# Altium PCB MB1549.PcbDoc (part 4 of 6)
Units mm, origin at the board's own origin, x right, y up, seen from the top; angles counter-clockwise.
Board outline 70 x 133.34 mm, 6 copper layers (Top Layer, Signal Layer 1, Signal Layer 2, Signal Layer 3, Signal Layer 4, Bottom Layer), stack 1.57 mm thick; 289 components, 250 nets, 1288 pads, 875 vias.
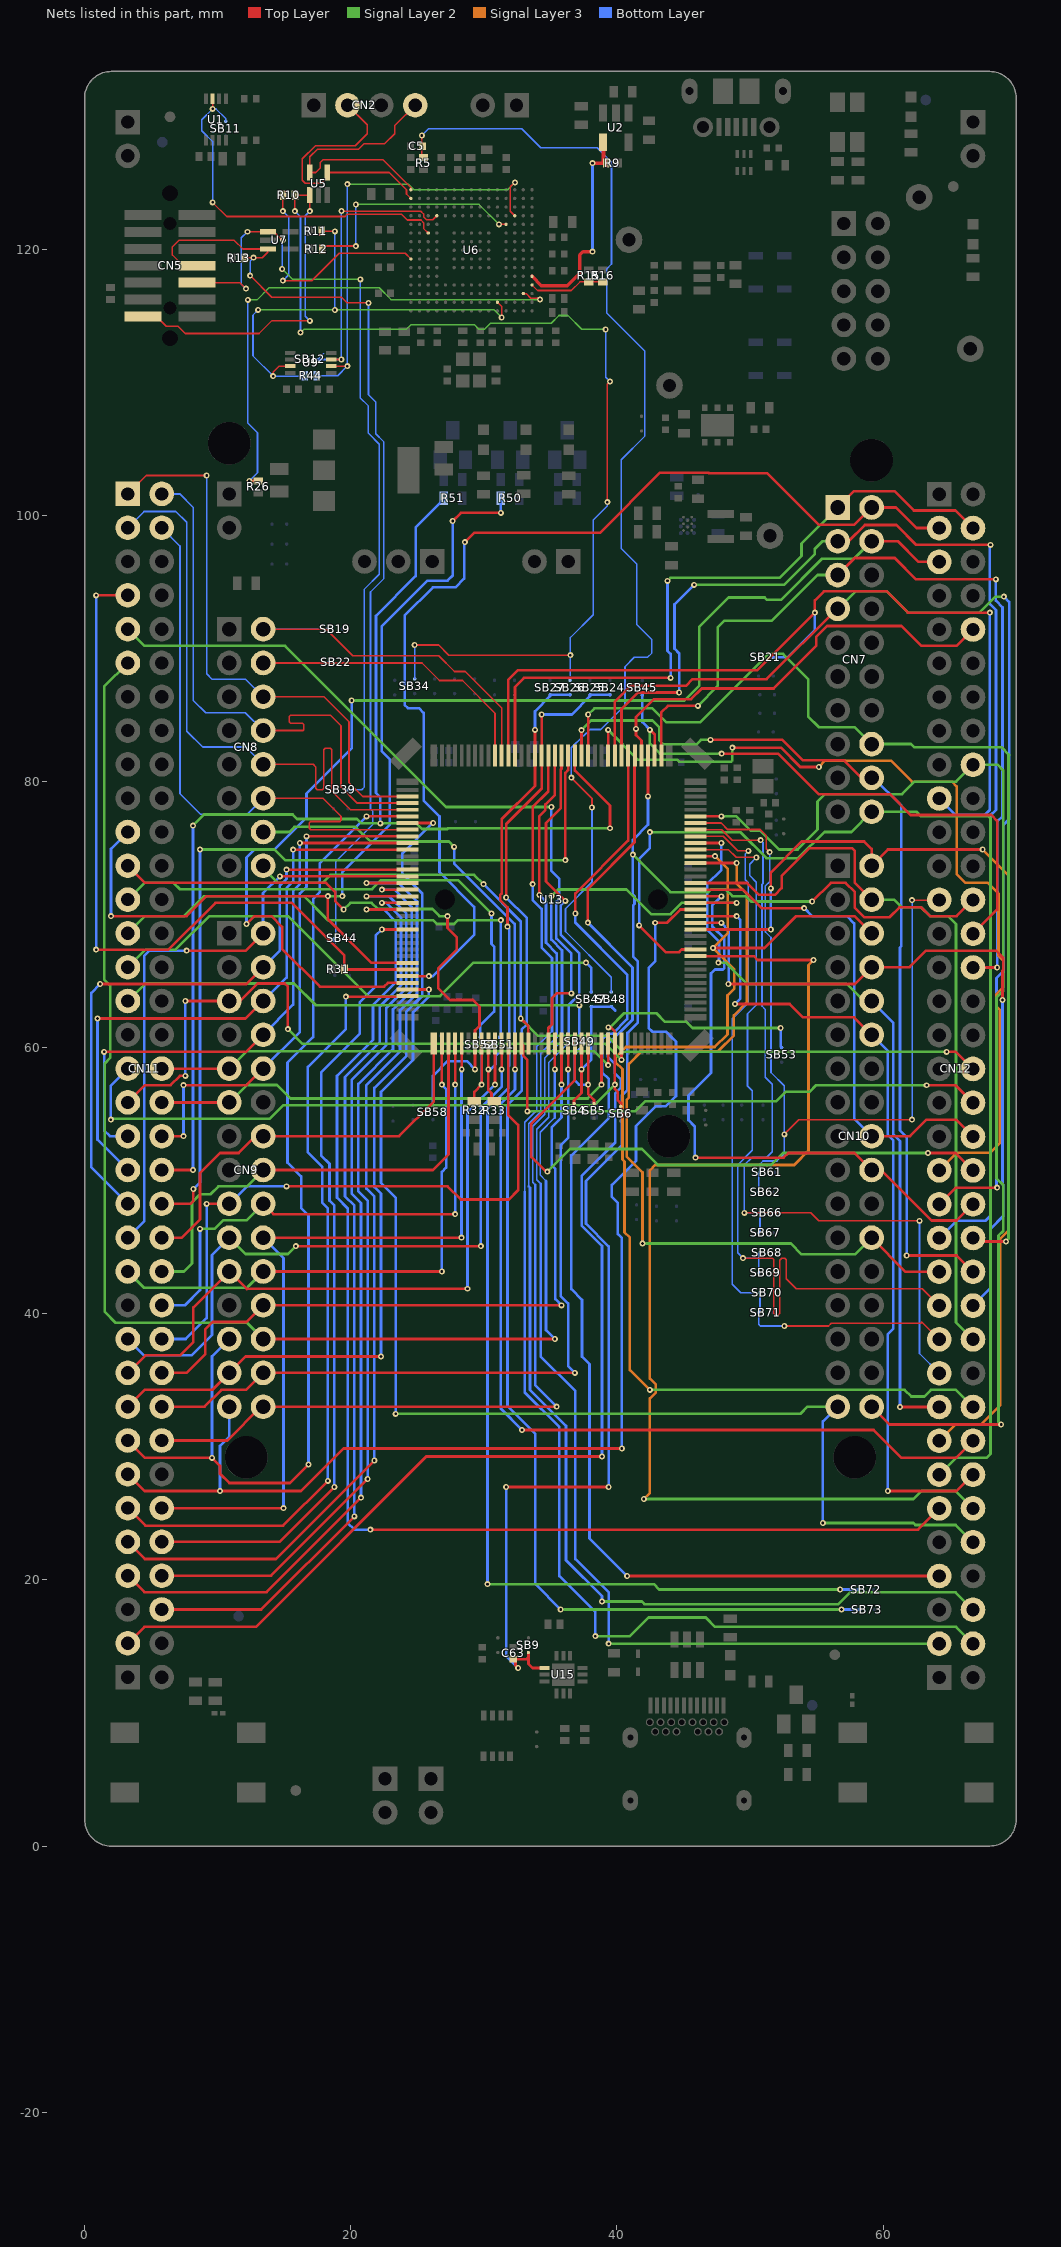
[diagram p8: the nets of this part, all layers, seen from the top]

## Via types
v1: diameter 0.45, hole 0.2, Top Layer to Bottom Layer, tented both sides, 875 vias

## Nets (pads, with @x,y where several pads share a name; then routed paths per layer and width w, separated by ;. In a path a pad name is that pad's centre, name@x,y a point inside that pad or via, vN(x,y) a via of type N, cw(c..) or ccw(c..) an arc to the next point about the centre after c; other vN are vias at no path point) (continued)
PB7: CN11.21 R50.1 U13.136 | length 71.9
  Top Layer w0.2: v1(1.98,69.881) 7.67,69.881 9.17,71.381 v1(18.27,71.381) 18.27,69.655 21.554,66.371 U13.136@24.262,66.371 ; v1(27.66,99.571) 28.27,100.181 v1(31.27,100.181)
  Signal Layer 2 w0.2: v1(18.27,71.381) v1(19.37,71.381)
  Bottom Layer w0.2: v1(1.98,69.881) 1.98,74.931 CN11.21@3.25,76.201 ; v1(19.37,71.381) 19.37,73.181 22.925,76.736 22.925,81.675 22.325,82.275 22.325,91.636 25.77,95.081 27.27,95.081 27.66,95.471 v1(27.66,99.571) ; v1(31.27,100.181) R50.1@31.27,101.281
PB8: CN7.2 CN12.3 U13.138 | length 81.9
  Top Layer w0.2: U13.138@24.262,65.371 v1(25.87,65.371) ; v1(28.57,97.981) 29.27,98.681 38.735,98.681 43.249,103.196 46.874,103.196 46.904,103.166 51.285,103.166 55.17,99.281 57.826,99.281 CN7.2@59.13,100.585 60.966,100.585 62.515,99.036 CN12.3@64.21,99.036
  Bottom Layer w0.2: v1(25.87,65.371) 26.164,65.371 29.27,68.477 29.27,70.581 26.67,73.181 26.67,77.381 25.47,78.581 25.47,85.155 25.125,85.5 24.3,85.5 24.05,85.75 24.05,92.461 26.17,94.581 27.87,94.581 28.518,95.229 28.518,97.929 v1(28.57,97.981)
PB9: CN7.4 CN12.5 U13.139 | length 89
  Top Layer w0.2: v1(12.17,69.281) 12.77,69.881 14.03,69.881 14.84,69.071 14.84,67.411 17.676,64.575 22.5,64.575 22.796,64.871 U13.139@24.237,64.871 ; CN7.4@59.13,98.045 61.106,98.045 62.655,96.496 CN12.5@64.21,96.496
  Signal Layer 2 w0.2: v1(20.07,86.081) 45.07,86.081 46.17,87.181 46.17,91.604 48.382,93.816 51.101,93.816 51.272,93.645 52.334,93.645 55.419,96.73 57.815,96.73 CN7.4@59.13,98.045
  Bottom Layer w0.2: v1(12.17,69.281) 12.17,74.286 12.77,74.886 14.275,74.886 16.67,77.281 16.67,79.081 20.07,82.481 v1(20.07,86.081)
PB10: CN12.25 SB61.1 SB62.2 U13.66 | length 63.4
  Top Layer w0.127: U13.66@45.912,76.871 47.839,76.871 48.329,76.381 50.77,76.381 51.217,75.934 51.217,74.934 v1(51.47,74.681) ; v1(52.57,53.481) 53.67,54.581 v1(62.17,54.581) ; v1(62.17,71.081) 64.195,71.081 CN12.25@64.21,71.096
  Bottom Layer w0.127: SB62.2@50.645,49.131 50.645,50.531 SB61.1@50.745,50.631 50.745,51.256 50.97,51.481 52.022,51.481 52.57,52.029 v1(52.57,53.481) 52.57,57.13 51.57,58.13 51.57,68.274 51.162,68.681 51.145,68.681 51.145,72.143 51.47,72.469 v1(51.47,74.681) ; v1(62.17,54.581) 62.186,54.597 62.186,71.066 v1(62.17,71.081)
PB11: CN10.34 CN12.18 U13.67 | length 88.3
  Top Layer w0.2: U13.67@45.937,77.371 v1(47.839,77.371) ; CN10.34@59.13,33.021 60.47,31.681 v1(68.87,31.681)
  Signal Layer 2 w0.2: v1(47.839,77.371) 47.861,77.394 48.958,77.394 50.07,76.281 50.77,76.281 52.17,74.881 53.57,74.881 55.07,76.381 55.07,78.481 55.629,79.04 61.429,79.04 62.37,79.981 65.475,79.981 CN12.18@66.75,81.256 68.595,81.256 69.022,80.829 69.022,64.272 68.518,63.768 68.518,50.172 69.022,49.668 69.022,46.233 68.67,45.881 68.67,31.881 v1(68.87,31.681)
PB13: CN7.5 CN12.30 U13.74 | length 68.1
  Top Layer w0.127: CN12.30@66.75,66.016 CN12.30@66.921,66.016
  Top Layer w0.2: U13.74@43.337,81.946 43.337,85.198 43.82,85.681 v1(46.07,85.681) ; CN7.5@56.59,95.505 57.866,96.781 60.87,96.781 62.47,95.181 v1(68.47,95.181) ; CN12.30@66.75,66.016 v1(68.57,66.016)
  Signal Layer 2 w0.2: v1(46.07,85.681) 47.57,87.181 47.57,91.581 48.063,92.074 51.64,92.074 55.071,95.505 CN7.5@56.59,95.505
  Bottom Layer w0.127: CN12.30@66.75,66.016 CN12.30@66.921,66.016
  Bottom Layer w0.2: v1(68.47,95.181) 68.47,93.581 68.97,93.081 68.97,77.381 68.57,76.981 v1(68.57,66.016)
PB14: CN12.28 SB45.2 U13.75 | length 43.7
  Top Layer w0.2: v1(42.47,83.881) 42.837,83.514 U13.75@42.837,81.971 ; v1(47.87,82.081) 52.109,82.081 55.15,79.04 60.511,79.04 62.07,77.481 68.13,77.481 68.57,77.041 68.57,70.376 CN12.28@66.75,68.556
  Signal Layer 2 w0.2: v1(42.47,83.881) 42.47,82.848 43.237,82.081 v1(47.87,82.081)
  Bottom Layer w0.2: SB45.2@41.9,86.475 41.9,84.451 v1(42.47,83.881)
PB15: C63.2 CN12.26 SB9.1 U13.76 U15.1 | length 114.5
  Top Layer w0.2: v1(31.67,26.981) v1(39.37,26.981) ; v1(32.57,13.381) 32.375,13.576 32.375,13.875 C63.2@32.2,14.05 33.2,14.05 33.35,14.2 ; SB9.1@33.35,14.55 33.35,14.2 ; U15.1@34.545,13.381 33.669,13.381 33.35,13.7 33.35,14.2 ; v1(42.337,78.881) U13.76@42.337,81.946 ; v1(54.67,70.981) 56.07,72.381 57.17,72.381 57.87,71.681 57.87,70.506 58.57,69.806 60.495,69.806 61.228,70.539 62.862,70.539 63.53,69.871 65.525,69.871 CN12.26@66.75,71.096
  Signal Layer 2 w0.2: v1(41.191,74.502) 44.012,71.681 46.87,71.681 47.07,71.881 48.17,71.881 48.67,71.381 49.67,71.381 50.07,70.981 v1(54.67,70.981)
  Bottom Layer w0.2: v1(31.67,26.981) 31.67,14.281 v1(32.57,13.381) ; v1(39.37,26.981) 39.37,45.072 37.67,46.772 37.67,49.981 40.37,52.681 40.37,56.42 40.782,56.832 40.782,61.107 41.57,61.895 41.57,66.481 41.218,66.833 41.218,70.69 41.322,70.794 41.322,71.381 41.191,71.512 v1(41.191,74.502) 41.191,75.602 42.337,76.748 v1(42.337,78.881)
PC0: CN9.11 CN11.38 U13.26 | length 37.5
  Top Layer w0.2: CN11.38@5.79,55.881 CN9.11@10.87,55.881 ; v1(38.837,57.214) U13.26@38.837,60.296
  Signal Layer 2 w0.2: CN9.11@10.87,55.881 12.185,57.196 14.455,57.196 15.474,56.177 37.8,56.177 v1(38.837,57.214)
PC1: CN9.9 CN11.36 U13.27 | length 36.1
  Top Layer w0.2: CN11.36@5.79,58.421 CN9.9@10.87,58.421 ; v1(39.337,58.681) U13.27@39.337,60.271
  Signal Layer 2 w0.2: CN9.9@10.87,58.421 12.185,59.736 38.282,59.736 v1(39.337,58.681)
PC2: CN11.35 SB6.1 SB53.1 U13.28 | length 65
  Top Layer w0.2: v1(39.352,61.528) 39.534,61.528 39.562,61.5 39.837,61.225 U13.28@39.837,60.296 v1(39.837,57.214) 39.837,56.887 40.07,56.654 40.07,56.032 40.321,55.781
  Signal Layer 2 w0.2: v1(1.97,54.581) 2.045,54.656 13.917,54.656 14.942,55.681 38.304,55.681 v1(39.837,57.214) ; v1(39.352,61.528) 39.39,61.528 39.418,61.5 39.437,61.481 40.537,62.581 42.969,62.581 43.612,61.938 45.213,61.938 45.676,61.475 v1(52.3,61.475)
  Bottom Layer w0.2: v1(1.97,54.581) 1.97,57.141 CN11.35@3.25,58.421 ; v1(52.3,61.475) 52.3,60.07 SB53.1@52.37,60
PC3: CN9.5 CN11.37 U13.29 | length 49.5
  Top Layer w0.2: CN11.37@3.25,55.881 4.55,57.181 6.47,57.181 7.17,57.881 v1(7.57,57.881) ; v1(7.57,63.501) CN9.5@10.87,63.501 11.678,63.501 12.993,64.816 15.035,64.816 15.27,64.581 v1(15.27,61.381) ; v1(40.337,59.081) U13.29@40.337,60.271
  Signal Layer 2 w0.2: v1(15.27,61.381) 16.37,60.281 39.137,60.281 v1(40.337,59.081)
  Bottom Layer w0.2: v1(7.57,57.881) v1(7.57,63.501)
PC6: CN7.1 CN12.4 U13.96 | length 51.9
  Top Layer w0.2: U13.96@32.337,81.946 32.337,87.098 33.02,87.781 v1(44.031,87.781) ; CN7.1@56.59,100.585 57.815,101.81 60.841,101.81 62.3,100.351 65.435,100.351 CN12.4@66.75,99.036
  Signal Layer 2 w0.2: v1(43.8,95.075) 44.021,95.296 52.223,95.296 53.87,96.944 53.87,97.865 CN7.1@56.59,100.585
  Bottom Layer w0.2: v1(43.8,95.075) 43.8,89.8 44.031,89.569 v1(44.031,87.781)
PC7: CN12.19 SB21.1 U13.97 | length 70.4
  Top Layer w0.2: U13.97@31.837,81.971 31.837,87.648 32.537,88.348 50.537,88.348 v1(54.87,92.681) 54.87,93.591 55.559,94.28 57.097,94.28 57.098,94.281 58.622,94.281 58.623,94.28 60.271,94.28 61.87,92.681 v1(68.02,92.681)
  Bottom Layer w0.2: SB21.1@51.737,89.318 52.807,89.318 54.87,91.381 v1(54.87,92.681) ; CN12.19@64.21,78.716 65.445,77.481 67.63,77.481 68.02,77.871 v1(68.02,92.681)
PC8: CN8.2 SB19.2 U13.98 | length 28.8
  Top Layer w0.127: CN8.2@13.41,91.441 18.15,91.441 20.141,89.45 26.601,89.45 27.795,88.256 28.595,88.256 31.337,85.514 U13.98@31.337,81.946
  Bottom Layer w0.127: CN8.2@13.41,91.441 SB19.2@18.27,91.441
PC9: CN8.4 SB22.1 U13.99 | length 27.2
  Top Layer w0.127: CN8.4@13.41,88.901 25.35,88.901 26.67,87.581 28.388,87.581 30.837,85.132 U13.99@30.837,81.946
  Bottom Layer w0.127: CN8.4@13.41,88.901 18.33,88.901 SB22.1@18.37,88.941
PC10: CN8.6 CN11.1 U13.111 | length 43
  Top Layer w0.127: CN11.1@3.25,101.601 4.63,102.981 v1(9.17,102.981) ; CN8.6@13.41,86.361 17.99,86.361 19.87,84.481 19.87,79.901 20.9,78.871 U13.111@24.262,78.871
  Bottom Layer w0.127: v1(9.17,102.981) 9.17,88.081 9.57,87.681 12.09,87.681 CN8.6@13.41,86.361
PC11: CN8.8 CN11.2 U13.112 | length 42.9
  Top Layer w0.127: CN8.8@13.41,83.821 16.41,83.821 16.47,83.881 16.47,84.281 16.37,84.381 15.47,84.381 15.37,84.481 15.37,84.881 15.47,84.981 18.47,84.981 19.27,84.181 19.27,79.581 20.48,78.371 U13.112@24.262,78.371
  Bottom Layer w0.127: CN11.2@5.79,101.601 7.15,101.601 8.17,100.581 8.17,86.081 9.09,85.161 12.07,85.161 CN8.8@13.41,83.821
PC12: CN8.10 CN11.3 U13.113 | length 47
  Top Layer w0.127: CN8.10@13.41,81.281 17.17,81.281 17.37,81.081 17.37,79.481 17.47,79.381 17.87,79.381 17.97,79.481 17.97,82.381 18.07,82.481 18.47,82.481 18.57,82.381 18.57,79.281 19.98,77.871 U13.113@24.262,77.871
  Bottom Layer w0.127: CN11.3@3.25,99.061 4.47,100.281 6.86,100.281 7.67,99.471 7.67,83.781 8.87,82.581 12.11,82.581 CN8.10@13.41,81.281
PC13: CN11.23 SB58.2 U13.7 | length 47.3
  Top Layer w0.2: CN11.23@3.25,73.661 4.53,72.381 18.144,72.381 18.825,71.7 18.825,71.026 v1(19.47,70.381) ; v1(27.27,69.881) 27.27,68.981 27.97,68.281 27.97,67.358 26.57,65.958 26.57,64.468 27.457,63.581 29.17,63.581 29.67,63.081 29.67,61.631 29.337,61.298 U13.7@29.337,60.296 ; v1(29.337,58.369) U13.7@29.337,60.271
  Signal Layer 2 w0.2: v1(19.47,70.381) 19.97,70.881 21.57,70.881 22.032,70.419 26.132,70.419 26.67,69.881 v1(27.27,69.881)
  Bottom Layer w0.2: SB58.2@26.17,55.681 26.17,57.881 27.27,58.981 28.725,58.981 v1(29.337,58.369)
PC14: CN11.25 SB52.2 | length 39.2
  Signal Layer 2 w0.2: CN11.25@3.25,71.121 4.51,72.381 6.67,72.381 7.15,71.901 21.59,71.901 22.27,72.581 28.06,72.581 v1(30.57,70.071)
  Bottom Layer w0.2: SB52.2@29.737,60.781 29.737,61.681 30.77,62.714 30.77,67.581 30.57,67.781 v1(30.57,70.071)
PC14-OSC32_IN: R32.1 SB52.1 U13.8 | length 7.1
  Top Layer w0.2: R32.1@29.287,55.977 29.287,56.664 v1(29.837,57.214) U13.8@29.837,60.296
  Bottom Layer w0.2: SB52.1@29.737,59.681 29.837,59.581 v1(29.837,57.214)
PC15: CN11.27 SB51.2 | length 39
  Signal Layer 2 w0.2: CN11.27@3.25,68.581 4.55,69.881 7.47,69.881 8.97,71.381 16.47,71.381 18.27,69.581 26.17,69.581 26.47,69.281 27.77,69.281 28.07,69.581 v1(31.27,69.581)
  Bottom Layer w0.2: SB51.2@31.17,60.781 31.27,60.881 v1(31.27,69.581)
PC15-OSC32_OUT: R33.1 SB51.1 U13.9 | length 6.2
  Top Layer w0.2: U13.9@30.337,60.271 v1(30.337,58.369) 30.337,56.804 30.57,56.571 30.57,56.186 R33.1@30.786,55.97
  Bottom Layer w0.2: v1(30.337,58.369) 30.493,58.369 30.87,58.746 30.87,59.381 SB51.1@31.17,59.681
PD0: CN9.25 CN11.57 U13.114 | length 80.2
  Top Layer w0.2: CN11.57@3.25,30.481 4.55,29.181 v1(9.57,29.181) 10.17,28.581 10.17,27.981 10.87,27.281 15.425,27.281 v1(16.825,28.681) ; v1(21.18,77.371) U13.114@24.262,77.371
  Bottom Layer w0.2: v1(9.57,29.181) 9.57,36.801 CN9.25@10.87,38.101 ; v1(16.825,28.681) 16.825,47.381 16.27,47.936 16.27,50.33 15.25,51.35 15.25,58.875 17.17,60.795 17.17,71.181 17.67,71.681 17.67,73.861 v1(21.18,77.371)
PD1: CN9.27 CN11.55 U13.115 | length 65.9
  Top Layer w0.2: CN11.55@3.25,33.021 4.51,34.281 9.59,34.281 CN9.27@10.87,35.561 12.095,36.786 v1(22.27,36.786) ; U13.115@24.287,76.871 v1(26.189,76.871)
  Bottom Layer w0.2: v1(22.27,36.786) 22.27,49.03 21.77,49.53 21.77,56.981 24.17,59.381 24.17,62.695 25.37,63.895 25.37,71.581 23.87,73.081 23.87,74.587 26.154,76.871 v1(26.189,76.871)
PD2: CN8.12 CN11.4 U13.116 | length 45
  Top Layer w0.127: CN8.12@13.41,78.741 17.91,78.741 19.27,77.381 19.27,77.081 19.17,76.981 16.97,76.981 16.87,76.881 16.87,76.481 16.98,76.371 U13.116@24.262,76.371
  Bottom Layer w0.127: CN11.4@5.79,99.061 7.17,97.681 7.17,79.081 8.71,77.541 12.21,77.541 CN8.12@13.41,78.741
PD3: CN9.10 CN11.40 U13.117 | length 38.3
  Top Layer w0.2: CN11.40@5.79,53.341 v1(7.43,53.341) ; v1(7.43,57.181) 12.17,57.181 CN9.10@13.41,58.421 ; v1(16.67,75.871) U13.117@24.237,75.871
  Bottom Layer w0.2: v1(7.43,53.341) v1(7.43,57.181) ; CN9.10@13.41,58.421 16.17,61.181 16.17,71.581 16.67,72.081 v1(16.67,75.871)
PD4: CN9.8 CN11.39 U13.118 | length 44
  Top Layer w0.2: v1(1.47,59.681) 12.13,59.681 CN9.8@13.41,60.961 ; v1(16.17,75.371) U13.118@24.262,75.371
  Bottom Layer w0.2: v1(1.47,59.681) 1.47,53.781 1.91,53.341 CN11.39@3.25,53.341 ; CN9.8@13.41,60.961 15.67,63.221 15.67,71.781 16.17,72.281 v1(16.17,75.371)
PD5: CN9.6 CN11.41 U13.119 | length 46.2
  Top Layer w0.2: v1(0.97,62.186) 12.095,62.186 CN9.6@13.41,63.501 ; v1(15.67,74.871) U13.119@24.237,74.871
  Bottom Layer w0.2: v1(0.97,62.186) 0.97,53.081 CN11.41@3.25,50.801 ; CN9.6@13.41,63.501 15.18,65.271 15.18,71.991 15.67,72.481 v1(15.67,74.871)
PD6: CN9.4 CN11.43 U13.122 | length 47.8
  Top Layer w0.2: v1(1.17,64.781) 12.15,64.781 CN9.4@13.41,66.041 ; v1(15.17,73.371) U13.122@24.262,73.371
  Bottom Layer w0.2: v1(1.17,64.781) 0.504,64.115 0.504,51.007 CN11.43@3.25,48.261 ; CN9.4@13.41,66.041 14.67,67.301 14.67,72.181 15.17,72.681 v1(15.17,73.371)
PD7: CN9.2 CN11.45 U13.123 | length 45.7
  Top Layer w0.2: v1(7.67,67.281) 12.11,67.281 CN9.2@13.41,68.581 ; v1(14.67,72.871) U13.123@24.237,72.871
  Bottom Layer w0.2: CN11.45@3.25,45.721 4.475,46.946 4.475,66.886 4.87,67.281 v1(7.67,67.281) ; CN9.2@13.41,68.581 13.41,71.611 v1(14.67,72.871)
PD8: CN12.10 U13.77 | length 32.7
  Top Layer w0.2: U13.77@41.837,81.971 41.837,83.063 41.425,83.475 v1(41.425,83.95) 41.425,84.836 42.77,86.181 45.57,86.181 46.37,86.981 51.77,86.981 54.97,90.181 54.97,90.866 55.785,91.681 61.37,91.681 62.87,90.181 65.515,90.181 CN12.10@66.75,91.416
PD9: CN11.69 U13.78 | length 100
  Top Layer w0.2: CN11.69@3.25,15.241 4.49,16.481 12.87,16.481 25.67,29.281 v1(38.87,29.281) ; v1(37.806,69.382) 37.806,71.917 41.318,75.429 41.318,81.927 U13.78@41.337,81.946
  Bottom Layer w0.2: v1(37.806,69.382) 41.17,66.017 41.17,62.092 39.3,60.222 39.3,59.347 39.825,58.822 39.825,58.1 40.282,57.643 40.282,56.957 39.87,56.545 39.87,52.873 37.343,50.346 37.343,46.637 38.87,45.11 v1(38.87,29.281)
PD10: CN12.65 U13.79 | length 92.4
  Top Layer w0.2: v1(36.87,70.081) 36.87,71.581 40.837,75.548 U13.79@40.837,81.946 ; v1(40.77,20.296) CN12.65@64.21,20.296
  Bottom Layer w0.2: v1(36.87,70.081) 36.87,69.381 40.77,65.481 40.77,62.145 39.661,61.036 39.305,61.036 38.892,60.623 38.892,58.133 39.385,57.64 39.385,54.706 36.57,51.891 36.57,41.845 37.37,41.045 37.37,36.781 37.939,36.213 37.939,23.128 v1(40.77,20.296)
PD11: CN7.3 CN12.45 U13.80 | length 97.5
  Top Layer w0.2: U13.80@40.337,81.946 40.337,85.448 41.57,86.681 v1(44.67,86.681) ; CN7.3@56.59,98.045 57.398,98.045 58.623,99.27 60.346,99.27 60.355,99.261 60.99,99.261 62.47,97.781 v1(68.07,97.781)
  Signal Layer 2 w0.2: v1(45.8,94.775) 45.806,94.781 52.57,94.781 54.87,97.081 54.87,97.481 55.434,98.045 CN7.3@56.59,98.045
  Bottom Layer w0.2: v1(44.67,86.681) 44.67,89.63 44.325,89.975 44.325,93.3 v1(45.8,94.775) ; CN12.45@64.21,45.696 65.495,46.981 67.67,46.981 68.07,47.381 68.07,77.459 68.472,77.861 68.472,92.868 68.018,93.322 68.018,97.729 v1(68.07,97.781)
PD12: CN7.7 CN12.43 U13.81 | length 87.7
  Top Layer w0.2: U13.81@39.837,81.971 39.837,85.998 41.02,87.181 45.17,87.181 45.67,87.681 51.231,87.681 56.515,92.965 CN7.7@56.59,92.965 ; CN12.43@64.21,48.236 65.455,49.481 v1(68.57,49.481)
  Signal Layer 2 w0.2: CN7.7@56.59,92.965 57.905,94.28 60.271,94.28 61.87,92.681 67.248,92.681 68.448,93.881 v1(69.07,93.881)
  Bottom Layer w0.2: v1(68.57,49.481) 68.518,49.533 68.518,65.229 69.022,65.733 69.022,76.733 69.47,77.181 69.47,93.481 v1(69.07,93.881)
PD13: CN12.41 U13.82 | length 66.7
  Top Layer w0.2: U13.82@39.337,81.946 v1(39.337,83.881) ; v1(48.67,82.533) 52.318,82.533 53.77,81.081 v1(55.17,81.081)
  Signal Layer 2 w0.2: v1(39.337,83.881) 41.597,81.621 44.53,81.621 44.67,81.481 48.57,81.481 48.67,81.581 v1(48.67,82.533)
  Signal Layer 3 w0.2: v1(55.17,81.081) 55.644,81.555 60.596,81.555 62.17,79.981 65.17,79.981 65.525,79.626 65.525,73.026 66.17,72.381 67.87,72.381 68.67,71.581 68.67,66.881 69.022,66.529 69.022,64.533 68.518,64.029 68.518,63.081 68.77,62.829 68.77,52.833 68.028,52.091 65.525,52.091 CN12.41@64.21,50.776
PD14: CN7.16 CN12.46 U13.85 | length 81.5
  Top Layer w0.2: U13.85@37.837,81.946 v1(37.837,85.028) ; CN12.46@66.75,45.696 67.012,45.434 v1(69.228,45.434)
  Signal Layer 2 w0.2: v1(37.837,85.028) 38.304,85.495 42.656,85.495 43.718,84.433 46.222,84.433 51.37,89.581 52.47,89.581 54.37,87.681 54.37,84.871 55.16,84.081 57.854,84.081 CN7.16@59.13,82.805 62.094,82.805 62.328,82.571 68.88,82.571 69.47,81.981 69.422,81.933 69.422,45.628 v1(69.228,45.434)
PD15: CN7.18 CN12.48 U13.86 | length 69.3
  Top Layer w0.2: U13.86@37.337,81.946 v1(37.337,83.848) ; v1(47.022,83.129) 52.422,83.129 53.971,81.58 57.071,81.58 58.386,80.265 CN7.18@59.13,80.265 ; v1(61.77,44.381) 65.525,44.381 CN12.48@66.75,43.156
  Signal Layer 2 w0.2: v1(37.337,83.848) 38.065,84.576 42.675,84.576 43.17,84.081 43.17,83.096 43.485,82.781 45.97,82.781 46.318,83.129 v1(47.022,83.129)
  Bottom Layer w0.2: CN7.18@59.13,80.265 59.286,80.265 61.37,78.181 61.37,67.628 61.266,67.524 61.266,53.785 61.77,53.281 v1(61.77,44.381)
PE0: CN10.33 CN12.64 U13.140 | length 90
  Top Layer w0.2: U13.140@24.262,64.371 v1(25.87,64.371)
  Signal Layer 2 w0.2: v1(23.37,32.481) 53.77,32.481 54.31,33.021 CN10.33@56.59,33.021 ; v1(55.47,24.281) 62.27,24.281 62.415,24.136 65.45,24.136 CN12.64@66.75,22.836
  Bottom Layer w0.2: v1(23.37,32.481) 23.37,48.73 22.27,49.83 22.27,56.681 24.67,59.081 24.67,62.645 25.87,63.845 v1(25.87,64.371) ; v1(55.47,24.281) 55.47,31.901 CN10.33@56.59,33.021
PE1: CN11.61 U13.141 | length 59.8
  Top Layer w0.2: CN11.61@3.25,25.401 4.565,24.086 14.911,24.086 v1(18.275,27.45) ; v1(19.625,63.825) 24.216,63.825 U13.141@24.262,63.871
  Bottom Layer w0.2: v1(18.275,27.45) 18.275,47.925 17.85,48.35 17.85,51.05 16.77,52.13 16.77,58.552 19.625,61.407 v1(19.625,63.825)
PE2: CN9.14 CN11.46 U13.1 | length 31.1
  Top Layer w0.2: CN11.46@5.79,45.721 7.31,45.721 8.67,47.081 8.67,50.581 10.17,52.081 11.57,52.081 12.83,53.341 CN9.14@13.41,53.341 23.63,53.341 26.237,55.948 U13.1@26.237,60.271
PE3: CN9.22 CN11.47 U13.2 | length 42
  Top Layer w0.2: CN9.22@13.41,43.181 v1(26.837,43.181) ; v1(26.837,57.214) U13.2@26.837,60.296
  Signal Layer 2 w0.2: CN11.47@3.25,43.181 4.475,41.956 12.185,41.956 CN9.22@13.41,43.181
  Bottom Layer w0.2: v1(26.837,43.181) 26.837,50.648 27.17,50.981 27.17,56.881 v1(26.837,57.214)
PE4: CN9.16 CN11.48 U13.3 | length 36.2
  Top Layer w0.2: CN9.16@13.41,50.801 26.17,50.801 27.337,51.968 U13.3@27.337,60.271
  Signal Layer 2 w0.2: CN11.48@5.79,43.181 7.47,43.181 8.07,43.781 8.07,48.381 8.67,48.981 9.47,48.981 10.065,49.576 12.185,49.576 CN9.16@13.41,50.801
PE5: CN9.18 CN11.50 U13.4 | length 41
  Top Layer w0.2: CN9.18@13.41,48.261 14.19,47.481 v1(27.837,47.481) ; v1(27.837,57.214) U13.4@27.837,60.296
  Signal Layer 2 w0.2: v1(8.67,46.381) 9.77,46.381 10.425,47.036 12.185,47.036 CN9.18@13.41,48.261
  Bottom Layer w0.2: CN11.50@5.79,40.641 7.53,40.641 8.67,41.781 v1(8.67,46.381) ; v1(27.837,47.481) v1(27.837,57.214)
PE6: CN9.20 CN11.62 U13.5 | length 59.6
  Top Layer w0.2: CN11.62@5.79,25.401 v1(14.95,25.401) ; CN9.20@13.41,45.721 v1(28.318,45.721) ; v1(28.337,58.369) U13.5@28.337,60.271
  Bottom Layer w0.2: CN9.20@13.41,45.721 14.95,44.181 v1(14.95,25.401) ; v1(28.318,45.721) 28.318,58.35 v1(28.337,58.369)
PE7: CN10.20 CN12.44 U13.55 | length 47.5
  Top Layer w0.2: v1(45.902,51.729) 52.522,51.729 52.874,52.081 57.85,52.081 CN10.20@59.13,50.801 59.85,50.801 63.64,47.011 65.525,47.011 CN12.44@66.75,48.236 ; U13.55@45.937,71.371 v1(47.839,71.371)
  Bottom Layer w0.2: v1(45.902,51.729) 45.843,51.788 45.843,54.075 45.37,54.548 45.37,56.395 47.07,58.095 47.07,65.581 47.36,65.871 47.96,65.871 48.068,65.979 48.068,68.183 47.17,69.081 47.17,70.702 v1(47.839,71.371)
PE8: CN10.18 CN12.40 U13.56 | length 38.2
  Top Layer w0.2: U13.56@45.912,71.871 49.48,71.871 50.87,70.481 v1(54.07,70.481) ; CN10.18@59.13,53.341 62.03,53.341 63.27,54.581 65.485,54.581 CN12.40@66.75,53.316
  Bottom Layer w0.2: v1(54.07,70.481) 54.67,69.881 57.27,69.881 57.815,69.336 57.815,54.656 CN10.18@59.13,53.341
PE9: CN10.4 CN12.52 U13.57 | length 57.4
  Top Layer w0.2: U13.57@45.937,72.371 49.78,72.371 50.67,71.481 51.87,71.481 52.37,71.981 52.37,72.881 54.47,74.981 57.67,74.981 57.87,74.781 57.87,72.381 CN10.4@59.13,71.121
  Signal Layer 2 w0.2: CN10.4@59.13,71.121 60.83,71.121 61.412,70.539 62.862,70.539 63.53,69.871 64.88,69.871 65.47,69.281 65.47,39.356 CN12.52@66.75,38.076
PE10: CN10.24 CN12.47 U13.60 | length 63.8
  Top Layer w0.2: U13.60@45.912,73.871 v1(48.994,73.871) ; CN10.24@59.13,45.721 61.695,43.156 CN12.47@64.21,43.156
  Signal Layer 2 w0.2: v1(41.922,45.281) 53.07,45.281 53.88,44.471 57.88,44.471 CN10.24@59.13,45.721
  Signal Layer 3 w0.2: v1(41.922,45.281) 41.922,50.629 40.73,51.821 40.73,56.075 40.892,56.237 40.892,58.765 41.852,59.725 47.6,59.725 48.775,60.9 48.775,62.425 49.775,63.425 49.775,71.55 48.994,72.331 v1(48.994,73.871)
PE11: CN10.6 CN12.56 U13.61 | length 90.4
  Top Layer w0.2: U13.61@45.937,74.371 45.947,74.381 v1(47.37,74.381) ; v1(47.211,67.481) 51.07,67.481 53.47,69.881 57.83,69.881 CN10.6@59.13,68.581
  Signal Layer 2 w0.2: v1(42.47,34.281) 61.618,34.281 62.118,33.781 63.09,33.781 63.59,34.281 65.465,34.281 CN12.56@66.75,32.996
  Signal Layer 3 w0.2: v1(42.47,34.281) 40.97,35.781 40.97,45.72 40.57,46.12 40.57,51.443 40.41,51.603 40.41,58.379 39.892,58.897 39.892,59.265 40.671,60.045 47.345,60.045 48.3,61 48.3,63.925 48.815,64.44 48.815,65.877 v1(47.211,67.481) 48.325,68.595 48.325,73.426 v1(47.37,74.381)
PE12: CN12.49 SB68.1 SB69.2 U13.62 | length 64.4
  Top Layer w0.127: U13.62@45.912,74.871 48.38,74.871 48.953,74.298 50.453,74.298 v1(50.47,74.281) ; v1(49.47,44.181) 51.669,44.181 51.775,44.075 51.775,40.05 51.925,39.9 52.1,39.9 52.225,40.025 52.225,44.025 52.375,44.175 52.6,44.175 52.725,44.05 52.725,42.626 53.47,41.881 62.945,41.881 CN12.49@64.21,40.616
  Bottom Layer w0.127: v1(50.47,74.281) 49.97,73.781 49.97,72.929 50.47,72.429 50.47,63.195 49.8,62.525 49.8,57.125 50.17,56.755 50.17,52.281 49.07,51.181 49.07,44.581 v1(49.47,44.181) 50.645,44.181 ; SB69.2@50.645,43.081 50.645,44.181 ; 50.67,44.181 50.645,44.181 ; SB68.1@50.745,44.581 50.645,44.481 50.645,44.181
PE13: CN10.10 CN12.55 U13.63 | length 58.9
  Top Layer w0.2: U13.63@45.937,75.371 v1(47.839,75.371) ; v1(61.27,32.996) CN12.55@64.21,32.996
  Signal Layer 2 w0.2: v1(47.616,66.381) 48.17,66.381 49.77,64.781 57.27,64.781 58.55,63.501 CN10.10@59.13,63.501
  Bottom Layer w0.2: v1(47.616,66.381) 47.67,66.435 47.67,67.981 46.77,68.881 46.77,72.281 47.839,73.35 v1(47.839,75.371) v1@47.721,75.371 ; CN10.10@59.13,63.501 60.77,61.861 60.77,53.481 61.27,52.981 v1(61.27,32.996)
PE14: CN12.51 SB70.1 SB71.2 U13.64 | length 56.4
  Top Layer w0.127: U13.64@45.912,75.871 47.98,75.871 49.07,74.781 v1(49.87,74.781) ; v1(52.57,39.081) 55.889,39.081 56.098,39.29 62.813,39.29 62.905,39.381 CN12.51@64.21,38.076
  Bottom Layer w0.127: v1(49.87,74.781) 49.637,74.548 49.637,72.614 49.87,72.381 49.87,63.37 48.67,62.17 48.67,56.469 48.668,56.467 48.668,42.213 49.3,41.581 50.395,41.581 ; SB70.1@50.745,41.581 50.745,40.181 SB71.2@50.645,40.081 50.645,39.206 50.77,39.081 v1(52.57,39.081)
PE15: CN12.53 SB66.1 SB67.2 U13.65 | length 63.3
  Top Layer w0.127: U13.65@45.912,76.371 47.88,76.371 48.67,75.581 v1(50.802,75.581) ; v1(49.57,47.581) 54.57,47.581 55.17,46.981 v1(62.73,46.981)
  Bottom Layer w0.127: SB67.2@50.645,46.081 50.745,46.181 SB66.1@50.745,47.581 v1(49.57,47.581) 49.57,51.181 50.155,51.766 51.255,51.766 51.672,52.183 51.672,56.467 51.67,56.469 51.67,57.255 51.15,57.775 51.15,62.866 50.891,63.125 50.891,72.248 50.97,72.328 50.97,75.413 v1(50.802,75.581) ; v1(62.73,46.981) 62.73,37.016 CN12.53@64.21,35.536
PF0: CN9.21 CN11.53 U13.10 | length 50
  Top Layer w0.2: CN11.53@3.25,35.561 4.565,36.876 7.165,36.876 8.17,37.881 8.17,40.481 CN9.21@10.87,43.181 12.185,41.866 12.2,41.881 v1(28.77,41.881) ; v1(30.837,57.214) U13.10@30.837,60.296
  Bottom Layer w0.2: v1(28.77,41.881) 28.77,55.147 v1(30.837,57.214)
PF1: CN9.19 CN11.51 U13.11 | length 50.8
  Top Layer w0.2: v1(15.87,45.081) v1(29.77,45.081) ; v1(31.337,58.369) U13.11@31.337,60.271
  Signal Layer 2 w0.2: CN9.19@10.87,45.721 12.095,44.496 15.285,44.496 v1(15.87,45.081)
  Bottom Layer w0.2: CN11.51@3.25,38.101 4.475,36.876 8.035,36.876 9.57,38.411 9.57,44.421 CN9.19@10.87,45.721 ; v1(29.77,45.081) 29.77,55.481 31.337,57.048 v1(31.337,58.369)
PF2: CN9.17 CN11.52 U13.12 | length 48.6
  Top Layer w0.2: v1(9.17,48.261) CN9.17@10.87,48.261 ; v1(15.17,49.581) 27.27,49.581 28.27,48.581 31.87,48.581 32.57,49.281 32.57,54.181 31.837,54.914 U13.12@31.837,60.296
  Bottom Layer w0.2: CN11.52@5.79,38.101 7.59,38.101 9.17,39.681 v1(9.17,48.261) ; CN9.17@10.87,48.261 12.185,49.576 15.165,49.576 v1(15.17,49.581)
PF3: CN8.14 CN12.58 U13.13 | length 99.1
  Top Layer w0.2: v1(32.337,58.369) U13.13@32.337,60.271 ; v1(32.87,31.266) 59.285,31.266 61.37,29.181 65.475,29.181 CN12.58@66.75,30.456
  Signal Layer 2 w0.2: CN8.14@13.41,76.201 15.39,76.201 15.77,76.581 20.37,76.581 21.47,75.481 27.37,75.481 v1(27.77,75.081)
  Bottom Layer w0.2: v1(27.77,75.081) 27.77,73.842 32.318,69.294 32.318,58.388 v1(32.337,58.369) 32.337,56.857 31.27,55.791 31.27,32.866 v1(32.87,31.266)
PF4: CN12.38 U13.14 | length 40.1
  Top Layer w0.2: U13.14@32.837,60.296 32.96,60.173 32.96,59.377 33.27,59.067 v1(33.27,55.214) ; v1(63.27,57.171) 65.435,57.171 CN12.38@66.75,55.856
  Signal Layer 2 w0.2: v1(33.27,55.214) 41.364,55.214 42.131,55.981 51.97,55.981 52.67,56.681 54.47,56.681 54.96,57.171 v1(63.27,57.171)
PF5: CN8.16 CN12.36 U13.15 | length 66.7
  Top Layer w0.2: v1(32.77,62.181) 33.337,61.614 U13.15@33.337,60.296 ; U13.15@33.324,60.284 U13.15@33.337,60.271 ; v1(64.77,59.681) 65.465,59.681 CN12.36@66.75,58.396
  Signal Layer 2 w0.2: CN8.16@13.41,73.661 13.41,73.492 14.521,72.381 17.88,72.381 18.48,72.981 29.27,72.981 v1(29.97,72.281) ; v1(32.77,62.181) 34.07,60.881 39.27,60.881 40.47,59.681 v1(64.77,59.681)
  Bottom Layer w0.2: v1(29.97,72.281) 32.77,69.481 v1(32.77,62.181)
PF6: CN11.9 U13.18 | length 57.3
  Top Layer w0.2: U13.18@34.837,60.296 34.837,61.455 35.118,61.736 35.118,63.729 35.47,64.081 v1(36.57,64.081)
  Signal Layer 2 w0.2: CN11.9@3.25,91.441 4.51,90.181 15.07,90.181 27.17,78.081 v1(35.07,78.081)
  Bottom Layer w0.2: v1(35.07,78.081) 35.07,73.281 35.67,72.681 35.67,71.181 35.443,70.954 35.443,68.198 36.57,67.071 v1(36.57,64.081)
PF7: CN9.26 CN11.11 U13.19 | length 107.6
  Top Layer w0.2: CN9.26@13.41,38.101 v1(35.337,38.101) ; v1(35.337,58.369) U13.19@35.337,60.271
  Signal Layer 2 w0.2: CN11.11@3.25,88.901 1.47,87.121 1.47,65.12 1.922,64.668 1.922,59.229 1.518,58.825 1.518,40.143 2.335,39.326 12.185,39.326 CN9.26@13.41,38.101
  Bottom Layer w0.127: 34.67,49.981 34.224,50.427 34.224,53.631 35.337,54.744
  Bottom Layer w0.2: 34.67,49.981 34.67,38.768 v1(35.337,38.101) ; 35.337,54.744 v1(35.337,58.369)
PF8: CN9.24 CN11.54 U13.20 | length 53.5
  Top Layer w0.2: CN11.54@5.79,35.561 7.65,35.561 9.07,36.981 9.07,38.841 9.61,39.381 12.15,39.381 CN9.24@13.41,40.641 v1(35.837,40.641) ; v1(35.837,57.214) U13.20@35.837,60.296
  Bottom Layer w0.2: v1(35.837,40.641) 35.37,41.108 35.37,50.881 35.09,51.161 35.09,54.001 35.837,54.748 v1(35.837,57.214)
PF9: CN9.28 CN11.56 U13.21 | length 57.5
  Top Layer w0.2: CN11.56@5.79,33.021 9.01,33.021 10.27,34.281 12.13,34.281 CN9.28@13.41,35.561 v1(36.837,35.561) ; v1(36.337,58.369) U13.21@36.337,60.271
  Bottom Layer w0.2: v1(36.337,58.369) 36.337,53.223 35.77,52.656 35.77,41.348 36.337,40.781 36.337,36.061 v1(36.837,35.561)
PF10: CN12.42 U13.22 | length 45.6
  Top Layer w0.2: v1(34.77,50.681) 34.67,50.681 33.57,51.781 33.57,54.281 36.837,57.548 U13.22@36.837,60.296 ; v1(63.37,52.081) 65.445,52.081 CN12.42@66.75,50.776
  Signal Layer 2 w0.2: v1(34.77,50.681) 36.47,52.381 41.87,52.381 43.07,51.181 51.57,51.181 52.47,52.081 v1(63.37,52.081)
PF11: CN12.62 U13.46 | length 86.8
  Top Layer w0.2: U13.46@45.912,66.871 50.28,66.871 50.57,66.581 v1(54.77,66.581)
  Signal Layer 2 w0.2: v1(42.018,26.081) 62.27,26.081 62.87,26.681 65.445,26.681 CN12.62@66.75,25.376
  Signal Layer 3 w0.2: v1(42.018,26.081) 42.47,26.533 42.47,33.642 42.915,34.087 42.915,34.685 42.47,35.13 42.47,50.781 42.87,51.181 53.319,51.181 54.394,52.256 54.394,66.205 v1(54.77,66.581)
PF12: CN7.20 CN12.59 U13.47 | length 92.8
  Top Layer w0.2: v1(41.67,69.181) 43.699,67.152 44.641,67.152 44.86,67.371 U13.47@45.912,67.371
  Signal Layer 2 w0.2: v1(42.47,76.181) 49.27,76.181 51.222,74.229 53.618,74.229 55.589,76.2 57.605,76.2 CN7.20@59.13,77.725 62.486,77.725 62.81,77.401 67.89,77.401 68.07,77.221 68.07,29.481 67.77,29.181 65.475,29.181 CN12.59@64.21,27.916
  Bottom Layer w0.2: v1(41.67,69.181) 41.67,74.181 42.47,74.981 v1(42.47,76.181)
PF13: CN10.2 CN12.57 U13.50 | length 77.3
  Top Layer w0.2: U13.50@45.912,68.871 v1(51.56,68.871) ; v1(51.56,71.971) 51.56,73.171 53.87,75.481 58.57,75.481 59.13,74.921 CN10.2@59.13,73.661 60.35,74.881 v1(67.47,74.881)
  Signal Layer 3 w0.2: CN12.57@64.21,30.456 65.435,31.681 67.34,31.681 68.776,33.118 68.776,45.621 69.422,46.267 69.422,72.929 v1(67.47,74.881)
  Bottom Layer w0.2: v1(51.56,68.871) v1(51.56,71.971)
PF14: CN10.8 CN12.50 U13.51 | length 55.7
  Top Layer w0.2: U13.51@45.937,69.371 v1(47.839,69.371) ; v1(48.37,64.781) 57.87,64.781 CN10.8@59.13,66.041 61.99,66.041 63.23,67.281 68.47,67.281 69.022,66.729 69.022,65.829 68.97,65.777 v1(68.97,63.581)
  Bottom Layer w0.2: v1(47.839,69.371) 48.395,68.815 48.395,64.806 v1(48.37,64.781) ; CN12.50@66.75,40.616 68.07,41.936 68.07,46.381 69.022,47.333 69.022,49.668 68.97,49.72 v1(68.97,63.581)
PF15: CN10.12 CN12.60 U13.52 | length 63.2
  Top Layer w0.2: U13.52@45.912,69.871 v1(48.994,69.871) ; v1(48.87,63.281) 52.97,63.281 53.975,62.276 57.815,62.276 CN10.12@59.13,60.961 ; v1(60.355,26.681) 65.515,26.681 CN12.60@66.75,27.916
  Bottom Layer w0.2: v1(48.87,63.281) 49.27,63.681 49.27,69.595 v1(48.994,69.871) ; CN10.12@59.13,60.961 60.355,59.736 60.355,53.434 60.77,53.019 60.77,38.881 60.355,38.466 v1(60.355,26.681)
PG0: CN9.29 CN11.59 U13.53 | length 93
  Top Layer w0.2: CN11.59@3.25,27.941 4.51,26.681 v1(10.17,26.681) 16.253,26.681 19.453,29.881 v1(40.37,29.881) ; v1(42.87,69.381) 43.77,69.381 44.76,70.371 U13.53@45.912,70.371
  Bottom Layer w0.2: v1(10.17,26.681) 10.17,30.081 10.87,30.781 CN9.29@10.87,33.021 ; v1(40.37,29.881) 40.37,45.681 40.07,45.981 40.07,48.329 39.618,48.781 39.618,49.681 41.429,51.492 41.425,51.497 41.425,54.1 42.925,55.6 43.675,55.6 44.43,56.355 44.43,60.445 44.159,60.716 44.153,60.716 43.705,61.164 43.705,61.17 43.679,61.196 42.65,61.196 42.385,61.461 42.385,65.996 42.87,66.481 v1(42.87,69.381)
PG1: CN9.30 CN11.58 U13.54 | length 89.4
  Top Layer w0.2: CN11.58@5.79,30.481 10.723,30.481 13.263,33.021 CN9.30@13.41,33.021 v1(35.47,33.021) ; U13.54@45.912,70.871 v1(48.994,70.871)
  Signal Layer 2 w0.2: v1(35.07,71.381) 35.57,71.881 40.718,71.881 42.57,70.029 44.018,70.029 44.86,70.871 v1(48.994,70.871)
  Bottom Layer w0.127: 33.87,49.681 33.67,49.881 33.67,54.081 34.57,54.981 34.57,59.214 35.87,60.514
  Bottom Layer w0.2: 33.87,49.681 33.87,34.621 v1(35.47,33.021) ; v1(35.07,71.381) 35.07,68.109 35.87,67.309 35.87,60.514
PG2: CN11.42 R51.1 U13.87 | length 93.6
  Top Layer w0.2: CN11.42@5.79,50.801 v1(8.15,50.801) ; U13.87@36.837,81.946 36.837,80.814 39.47,78.181 v1(39.47,76.481)
  Signal Layer 2 w0.2: v1(8.15,76.681) 8.985,77.516 15.635,77.516 15.97,77.181 20.47,77.181 20.801,76.85 v1(22.225,76.85) 24.925,76.85 25.349,76.426 27.265,76.426 27.32,76.481 v1(39.47,76.481)
  Bottom Layer w0.2: v1(8.15,50.801) v1(8.15,76.681) ; v1(22.225,76.85) 22.225,78.8 21.89,79.135 21.89,92.44 24.875,95.425 24.875,99.075 26.97,101.17 R51.1@26.97,101.281
PG3: CN11.44 U13.88 | length 64.8
  Top Layer w0.2: CN11.44@5.79,48.261 7.95,48.261 8.17,48.481 v1(8.17,49.381) ; v1(36.118,74.081) 36.118,80.629 36.337,80.848 U13.88@36.337,81.946
  Signal Layer 2 w0.2: v1(8.67,74.881) 8.675,74.886 14.265,74.886 15.07,74.081 v1(36.118,74.081)
  Bottom Layer w0.2: v1(8.17,49.381) 8.67,49.881 v1(8.67,74.881)
PG4: CN12.69 U13.89 | length 96.9
  Top Layer w0.2: U13.89@35.837,81.946 35.837,80.948 35.77,80.881 35.77,77.981 34.67,76.881 34.67,72.481 v1(36.124,71.027)
  Signal Layer 2 w0.2: v1(39.37,15.216) CN12.69@64.21,15.216
  Bottom Layer w0.127: 34.27,49.781 33.97,50.081 33.97,53.875 34.87,54.775 34.87,58.881 36.37,60.381
  Bottom Layer w0.2: 34.27,49.781 34.27,36.781 36.87,34.181 36.87,21.581 39.37,19.081 v1(39.37,15.216) ; v1(36.124,71.027) 35.77,70.674 35.77,68.481 37.17,67.081 37.17,63.981 36.37,63.181 36.37,60.381
PG5: CN12.68 U13.90 | length 96.6
  Top Layer w0.2: v1(34.17,71.481) 34.17,77.394 34.618,77.842 34.618,78.268 35.337,78.987 U13.90@35.337,81.946
  Signal Layer 2 w0.2: v1(38.87,18.381) 41.87,18.381 42.07,18.181 56.631,18.181 56.831,18.381 57.521,19.071 65.435,19.071 CN12.68@66.75,17.756
  Bottom Layer w0.127: 33.37,49.581 33.37,54.281 34.27,55.181 34.27,59.581 35.47,60.781
  Bottom Layer w0.2: 33.37,49.581 33.47,49.481 33.47,34.281 36.17,31.581 36.17,21.481 38.87,18.781 v1(38.87,18.381) ; v1(34.17,71.481) 34.67,70.981 34.67,67.881 35.47,67.081 35.47,60.781
PG6: CN12.70 U13.91 | length 100.1
  Top Layer w0.2: v1(33.67,72.281) 33.67,78.081 34.837,79.248 U13.91@34.837,81.946
  Signal Layer 2 w0.2: v1(38.37,15.781) 40.97,15.781 42.37,17.181 46.67,17.181 47.37,16.481 65.485,16.481 CN12.70@66.75,15.216
  Bottom Layer w0.127: 33.07,49.181 33.07,54.381 33.97,55.281 33.97,60.081 35.118,61.229
  Bottom Layer w0.2: 33.07,49.181 33.07,34.081 35.67,31.481 35.67,20.281 38.37,17.581 v1(38.37,15.781) ; v1(33.67,72.281) 33.67,71.081 34.343,70.408 34.343,67.508 35.118,66.733 35.118,61.229
PG7: SB24.2 SB25.2 SB73.1 U13.92 | length 99.6
  Top Layer w0.2: v1(31.67,71.281) 31.67,76.781 34.337,79.448 U13.92@34.337,81.946 v1(34.337,85.028)
  Signal Layer 2 w0.2: v1(35.77,17.781) v1(56.87,17.781)
  Bottom Layer w0.2: v1(31.67,71.281) 33.222,69.729 33.222,61.733 32.837,61.348 32.837,56.748 31.77,55.681 31.77,33.081 33.87,30.981 33.87,19.681 v1(35.77,17.781) ; v1(34.337,85.028) 36.603,85.028 37.975,86.4 SB25.2@37.975,86.5 SB24.2@39.475,86.5 ; v1(56.87,17.781) SB73.1@58.27,17.781
PG8: SB26.2 SB27.2 SB72.2 U13.93 | length 98.9
  Top Layer w0.2: v1(31.77,69.081) 31.77,70.542 31.218,71.094 31.218,71.468 31.343,71.593 31.343,77.173 33.837,79.667 U13.93@33.837,81.946 ; U13.93@33.837,81.971 v1(33.837,83.873)
  Signal Layer 2 w0.2: v1(30.27,19.681) 42.77,19.681 43.17,19.281 v1(56.77,19.281)
  Bottom Layer w0.2: v1(30.27,19.681) 30.27,55.381 31.837,56.948 31.837,58.581 31.897,58.641 31.897,68.954 v1(31.77,69.081) ; v1(33.837,83.873) 33.837,85.262 34.975,86.4 SB27.2@34.975,86.5 SB26.2@36.475,86.5 ; v1(56.77,19.281) SB72.2@58.17,19.281
PG9: CN11.63 U13.124 | length 73.4
  Top Layer w0.2: CN11.63@3.25,22.861 4.53,21.581 14.37,21.581 v1(21.77,28.981) ; v1(21.18,72.371) U13.124@24.262,72.371
  Bottom Layer w0.2: v1(21.18,72.371) 23.587,72.371 24.97,70.988 24.97,64.07 23.697,62.797 23.697,59.708 21.17,57.181 21.17,49.405 21.77,48.805 v1(21.77,28.981)
PG10: CN11.66 U13.125 | length 68.1
  Top Layer w0.2: CN11.66@5.79,20.321 14.01,20.321 v1(21.27,27.581) ; v1(22.335,71.871) U13.125@24.237,71.871
  Bottom Layer w0.2: v1(21.27,27.581) 21.27,48.505 20.57,49.205 20.57,57.281 23.17,59.881 23.17,62.87 24.57,64.27 24.57,70.571 23.27,71.871 v1(22.335,71.871)
PG12: CN11.65 U13.126 | length 73.5
  Top Layer w0.2: CN11.65@3.25,20.321 4.49,19.081 13.67,19.081 v1(20.77,26.181) ; v1(21.18,71.371) U13.126@24.262,71.371
  Bottom Layer w0.2: v1(20.77,26.181) 20.77,48.33 20.07,49.03 20.07,57.581 22.67,60.181 22.67,62.995 24.17,64.495 24.17,70.081 22.88,71.371 v1(21.18,71.371)
PG13: CN11.68 U13.127 | length 68.2
  Top Layer w0.2: CN11.68@5.79,17.781 13.27,17.781 v1(20.27,24.781) ; v1(22.335,70.871) U13.127@24.237,70.871
  Bottom Layer w0.2: v1(20.27,24.781) 20.27,48.13 19.57,48.83 19.57,57.781 22.17,60.381 22.17,63.07 23.77,64.67 23.77,69.771 22.67,70.871 v1(22.335,70.871)
PG14: CN12.61 U13.128 | length 98.3
  Top Layer w0.2: v1(21.18,70.371) U13.128@24.262,70.371 ; v1(21.47,23.781) 62.615,23.781 CN12.61@64.21,25.376
  Bottom Layer w0.2: v1(21.18,70.371) 22.48,70.371 23.37,69.481 23.37,64.895 21.67,63.195 21.67,60.581 18.97,57.881 18.97,48.73 19.77,47.93 19.77,24.281 20.27,23.781 v1(21.47,23.781)
PG15: CN11.64 U13.131 | length 60.8
  Top Layer w0.2: CN11.64@5.79,22.861 14.65,22.861 v1(18.77,26.981) ; v1(22.335,68.871) U13.131@24.237,68.871
  Bottom Layer w0.2: v1(18.77,26.981) 18.77,48.13 18.401,48.499 18.401,51.274 17.77,51.905 17.77,58.136 20.67,61.036 20.67,63.395 21.87,64.595 21.87,68.406 v1(22.335,68.871)
PH0: CN11.29 SB47.2 | length 41.9
  Signal Layer 2 w0.2: CN11.29@3.25,66.041 4.565,67.356 6.845,67.356 9.37,69.881 15.294,69.881 21.305,63.87 26.72,63.87 29.231,66.381 v1(37.67,66.381)
  Bottom Layer w0.2: v1(37.67,66.381) 38.07,65.981 SB47.2@38.07,64.181
PH0-OSC_IN: SB4.1 SB47.1 SB48.1 U13.23 | length 11.9
  Top Layer w0.2: 36.77,55.581 36.77,55.796 36.77,56.032 37.337,56.598 v1(37.337,58.369) U13.23@37.337,60.271
  Bottom Layer w0.2: v1(37.337,58.369) 38.07,59.102 SB47.1@38.07,63.081 SB48.1@39.57,63.081 39.87,62.781
PH1: CN11.31 SB49.2 | length 37.4
  Signal Layer 2 w0.2: CN11.31@3.25,63.501 4.565,64.816 15.735,64.816 17.37,63.181 v1(37.17,63.181)
  Bottom Layer w0.2: v1(37.17,63.181) 37.17,61.013 SB49.2@37.202,60.981
PH1-OSC_OUT: SB5.1 SB49.1 U13.24 | length 8.3
  Top Layer w0.2: U13.24@37.837,60.296 v1(37.837,57.214) 37.837,56.514 38.279,56.073 SB5.1@38.279,55.796
  Bottom Layer w0.2: SB49.1@37.202,59.881 36.837,59.516 36.837,57.514 37.137,57.214 v1(37.837,57.214)
PH3-BOOT0: CN11.7 R31.1 U13.137 | length 56.5
  Top Layer w0.2: v1(0.87,67.356) 6.297,67.356 9.822,70.881 15.57,70.881 19.52,66.931 R31.1@19.52,65.881 19.53,65.871 U13.137@24.237,65.871 ; v1(0.87,93.981) CN11.7@3.25,93.981
  Bottom Layer w0.2: v1(0.87,67.356) v1(0.87,93.981)
STLK_MCO: C5.2 R5.2 SB48.2 | length 89
  Top Layer w0.12: v1(25.341,128.529) 25.341,127.729 25.341,127.004 R5.2@25.466,126.879
  Top Layer w0.127: v1(36.57,80.281) 38.117,78.735 v1(38.117,78.035)
  Bottom Layer w0.12: v1(25.341,128.529) 25.841,129.029 32.841,129.029 34.266,127.604 38.516,127.604 39.591,126.529 39.591,118.868 39.225,118.502 39.225,115.195 42.1,112.32 42.1,105.95 40.325,104.175 40.325,97.5 41.5,96.325 41.5,91.775 42.625,90.65 42.625,89.65 42.3,89.325 41.3,89.325 40.6,88.625 40.6,85.722 38.778,83.9 37.967,83.9 37.506,83.439 37.489,83.439 36.57,82.52 v1(36.57,80.281)
  Bottom Layer w0.127: v1(38.117,78.035) 38.117,72.428 36.127,70.439 36.127,68.724 39.57,65.281 SB48.2@39.57,64.181
STLK_SWCLK: CN2.2 U5.4 U6.A14 | length 19.8
  Top Layer w0.12: CN2.2@19.756,130.809 21.229,129.336 21.229,128.672 20.327,127.77 17.345,127.77 16.35,126.775 16.35,125.175 16.575,124.95 17.788,124.95 18.225,125.387 U5.4@18.225,125.75 22.881,125.75 24.184,124.447 24.184,124.136 U6.A14@24.516,123.804
STLK_SWDIO: CN2.4 U5.5 U6.A15 | length 19.9
  Top Layer w0.12: U5.5@16.925,125.75 17.374,125.75 17.695,126.071 17.695,126.485 17.91,126.7 22.42,126.7 24.516,124.604 U6.A15@24.516,124.454 ; U5.5@16.925,126.1 16.925,126.925 17.5,127.5 20.575,127.5 20.984,127.909 22.541,127.909 23.303,128.672 23.303,129.276 CN2.4@24.836,130.809
STLK_VCP_RX: SB11.1 U1.3 U6.C10 | length 27.5
  Top Layer w0.12: v1(9.616,123.504) 10.676,122.444 19.566,122.444 19.731,122.609 23.811,122.609 24.241,122.179 25.272,122.179 25.471,121.98 25.471,121.549 U6.C10@25.816,121.204 ; v1(9.616,130.529) U1.3@9.616,131.279
  Bottom Layer w0.12: v1(9.616,123.504) 9.616,128.079 8.8,128.895 8.8,129.713 v1(9.616,130.529) 9.871,130.529 10.6,129.8 SB11.1@10.6,129.6
STLK_VCP_TX: R10.1 U6.A7 | length 17.4
  Top Layer w0.12: v1(14.9,117.625) 17.075,117.625 19.129,119.679 24.091,119.679 U6.A7@24.516,119.254 ; v1(14.9,122.849) R10.1@14.9,124.05
  Bottom Layer w0.12: v1(14.9,117.625) 15.346,118.071 15.346,122.403 v1(14.9,122.849)
T_JTDI: CN5.10 SB39.1 U7.1 | length 60.3
  Top Layer w0.12: CN5.10@8.453,117.474 11.676,117.474 v1(12.125,117.025) ; v1@12.229,121.304 12.234,121.304 U7.1@13.766,121.304 14.216,121.304 14.841,120.679 v1(14.916,120.679)
  Signal Layer 2 w0.12: v1(14.841,118.504) 15.616,117.729 v1(20.716,117.729)
  Bottom Layer w0.12: v1(12.125,117.025) 11.775,117.375 11.775,120.84 v1(12.234,121.299) ; v1(14.841,118.504) 14.841,120.604 v1(14.916,120.679) ; SB39.1@19.8,79.371 20.813,79.371 21.025,79.583 21.025,94.45 22.135,95.56 22.135,105.34 21.325,106.15 21.325,108.207 20.716,108.816 v1(20.716,117.729)
T_NRSTa: R26.1 U6.P3 | length 39
  Top Layer w0.12: U6.P3@32.966,116.654 33.185,116.654 33.53,116.309 34.111,116.309 v1(34.216,116.204)
  Top Layer w0.2: v1(12.375,102.575) R26.1@13.05,102.575
  Signal Layer 2 w0.12: v1(12.266,116.179) 12.954,116.179 13.859,117.084 22.134,117.084 23.014,116.204 v1(34.216,116.204)
  Bottom Layer w0.12: v1(12.266,116.179) 12.266,106.929 12.991,106.204 12.991,103.191 v1(12.375,102.575)
T_PWR_EN: R9.1 U2.4 U6.R5 | length 15.7
  Top Layer w0.25: U6.R5@33.616,117.954 34.316,117.254 36.266,117.254 37.191,118.179 37.191,119.554 37.441,119.804 v1(38.166,119.804) ; v1(38.166,126.454) 38.969,126.454 R9.1@38.973,126.459
  Top Layer w0.3: U2.4@38.966,128.014 38.973,128.006 R9.1@38.973,126.459
  Bottom Layer w0.25: v1(38.166,119.804) v1(38.166,126.454)
T_PWR_EXT: R15.2 R16.2 U6.R4 | length 5.8
  Top Layer w0.12: U6.R4@33.616,117.304 34.036,116.884 36.571,116.884 37.216,117.529 R15.2@37.891,117.529 R16.2@38.941,117.529
T_SWCLKa: R12.1 U6.M11 | length 17.7
  Top Layer w0.12: R12.1@17.85,119.975 18.1,120.225 v1@20.375,120.225 ; v1(31.141,121.854) U6.M11@31.666,121.854
  Signal Layer 2 w0.12: v1@20.38,123.329 20.392,123.341 20.405,123.354 29.641,123.354 v1(31.141,121.854)
  Bottom Layer w0.12: v1(20.38,120.22) 20.38,123.349 v1@20.38,123.354
  other v1: 20.385,123.349
T_SWDIO_IN: R44.2 U6.N12 U9.2 | length 33.3
  Top Layer w0.12: U9.2@18.541,111.204 v1(19.741,111.204) ; U6.N12@32.316,122.504 31.991,122.829 31.991,124.679 32.316,125.004 v1(32.341,125.004)
  Signal Layer 2 w0.12: v1(19.741,124.874) 24.321,124.874 24.741,124.454 31.791,124.454 v1(32.341,125.004)
  Bottom Layer w0.12: R44.2@17.441,110.479 19.016,110.479 v1(19.741,111.204) v1(19.741,124.874)
T_SWDIOa: R11.2 R44.1 U6.L2 U9.7 | length 36.6
  Top Layer w0.12: v1(14.166,110.454) 14.166,110.754 14.616,111.204 U9.7@15.441,111.204 ; R11.2@17.825,121.325 v1(18.805,121.325) ; U6.L2@31.016,116.004 31.341,115.679 v1(31.341,114.854)
  Signal Layer 2 w0.12: v1(13.041,115.429) 18.805,115.429 30.766,115.429 v1(31.341,114.854)
  Bottom Layer w0.12: v1(13.041,115.429) 12.65,115.038 12.65,111.97 v1(14.166,110.454) 16.516,110.454 R44.1@16.541,110.479 ; v1(18.805,115.424) v1(18.805,121.325)
T_SWO: CN5.8 R13.1 SB44.1 U7.3 | length 74.7
  Top Layer w0.12: CN5.8@8.453,118.744 7.406,118.744 6.6,119.55 6.6,120.181 7.069,120.65 11.25,120.65 11.896,120.004 U7.3@13.766,120.004 13.766,119.766 13.354,119.354 v1(12.691,119.354) 12.054,119.354 R13.1@12.025,119.325 ; v1(12.441,118.004) 14.07,116.375 19.3,116.375 19.725,115.95 v1@21.325,115.95
  Bottom Layer w0.12: v1(12.441,118.004) 12.441,119.104 v1(12.691,119.354) ; 18.37,68.381 18.676,68.076 18.87,67.881 18.87,68.2 18.87,73.981 21.664,76.775 21.664,77.75 21.48,77.935 21.48,94.23 22.465,95.215 22.465,105.535 21.875,106.125 21.875,108.5 21.33,109.045 v1(21.33,115.945)
T_SWOa: SB12.1 U6.D12 U9.3 | length 22
  Top Layer w0.12: U9.3@18.541,111.704 v1(19.291,111.704) ; v1(19.3,122.854) v1@19.366,122.854 ; v1@19.366,122.849 25.252,122.849 25.471,122.63 25.471,122.418 25.69,122.199 26.161,122.199 U6.D12@26.466,122.504
  Bottom Layer w0.12: 17.946,112.134 SB12.1@17.516,111.704 v1(19.291,111.704) 19.291,122.854 19.291,122.879 19.3,122.87 v1(19.3,122.854)
T_VCP_RX: CN5.13 R10.2 SB26.1 SB34.2 U5.1 | length 101
  Top Layer w0.12: CN5.13@4.389,114.934 5.391,114.934 6.125,114.2 7.025,114.2 7.571,113.654 13.104,113.654 14.05,114.6 v1(16.925,114.6) ; v1(15.8,122.849) R10.2@15.8,124.05 U5.1@16.925,124.05 v1(16.925,122.849) ; v1(24.8,90.25) 26.6,90.25 27.369,89.481 v1(36.5,89.481) ; v1(39.27,100.981) 39.27,109.845 v1(39.475,110.05)
  Signal Layer 2 w0.12: v1(16.225,113.725) 16.479,113.979 24.191,113.979 24.536,114.324 29.271,114.324 29.616,113.979 30.041,113.979 30.496,114.434 35.061,114.434 35.636,115.009 36.313,115.009 37.358,113.964 39.136,113.964 v1(39.15,113.95)
  Bottom Layer w0.12: v1(15.8,122.849) 16.225,122.424 v1(16.225,113.725) ; v1(16.925,114.6) 16.575,114.95 16.575,122.499 v1(16.925,122.849) ; SB34.2@24.8,87.7 v1(24.8,90.25) ; 36.5,87.925 v1(36.5,89.481) 36.5,90.814 38.218,92.532 38.218,99.649 39.27,100.701 v1(39.27,100.981) ; v1(39.15,113.95) 39.15,110.375 v1(39.475,110.05)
